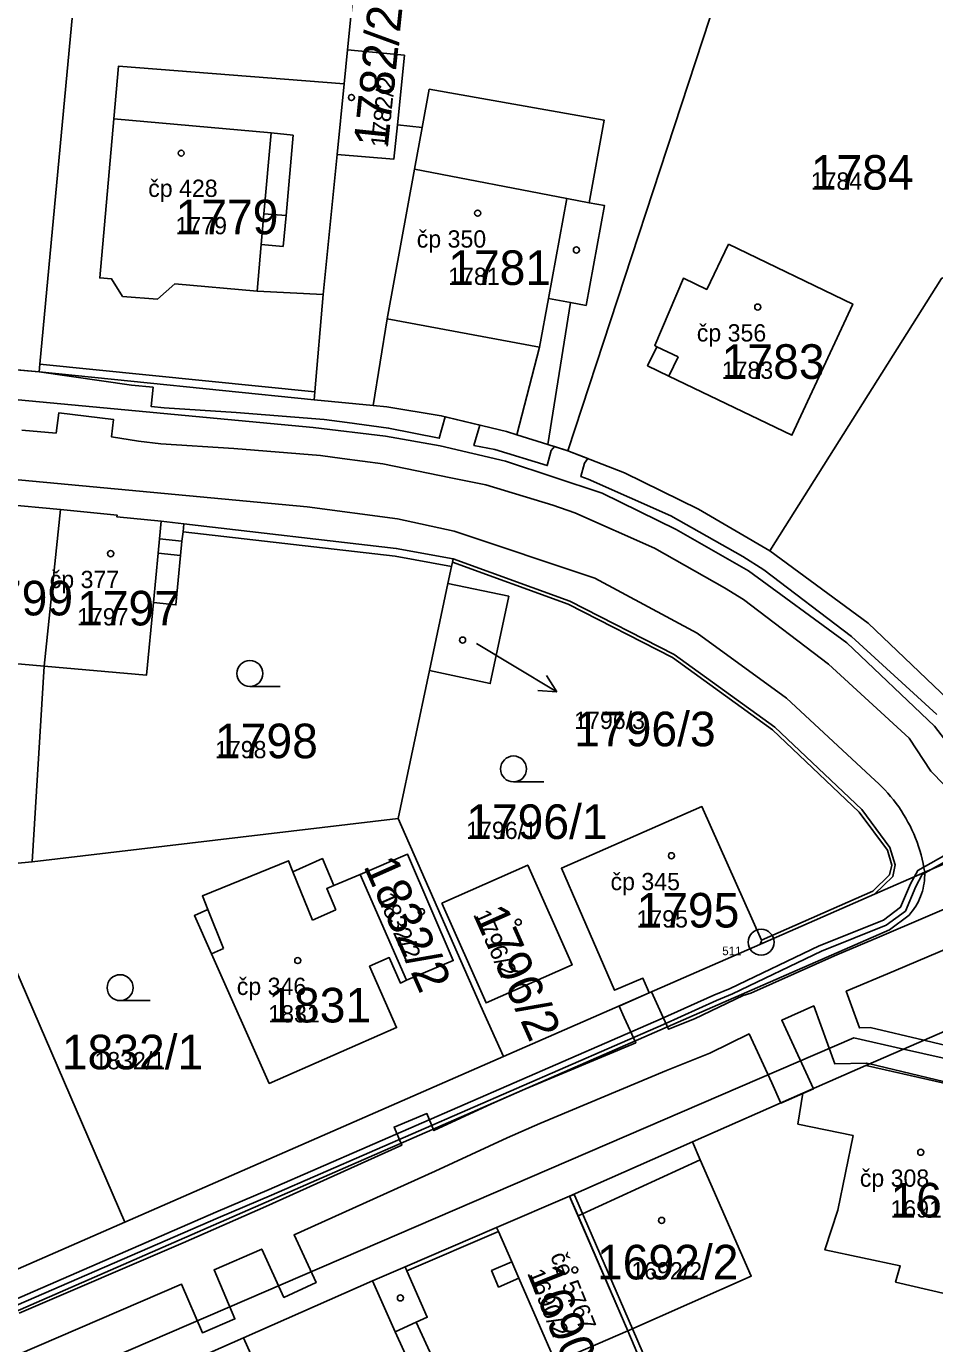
# Model space of a CAD drawing. Extents: x -763628 to -761565, y -976033 to -973833.
# Drawn here: x -762577.9 to -762525.4, y -975069 to -974992.9 of the extents above; entities that cross this region are included whole.
import ezdxf

# ---------------------------------------------------------------- set-up
doc = ezdxf.new("R2010")
doc.units = 0
for name, color, linetype in [('KN_cisla parcel 1000', 7, 'Continuous'), ('KN_cisla parcel 500', 7, 'Continuous'), ('KN_cisla parcel znacky', 7, 'Continuous'), ('KN_cisla popisna 500', 7, 'Continuous'), ('KN_hranice parcel', 7, 'Continuous'), ('KN_vecna bremena', 7, 'Continuous'), ('KN_vnitrni kresba parcel', 7, 'Continuous'), ('KN_znacky bodu BP', 7, 'Continuous'), ('KN_znacky budov', 7, 'Continuous'), ('KN_znacky kultur', 7, 'Continuous')]:
    doc.layers.add(name, color=color, linetype=linetype)

msp = doc.modelspace()

# ---------------------------------------------------------------- linework, layer by layer
at = {"layer": 'KN_cisla parcel znacky'}
for p, q in [((-762551.91, -975028.54), (-762549.82, -975029.8)), ((-762549.82, -975029.8), (-762547.248, -975031.346)), ((-762547.248, -975031.346), (-762547.848, -975030.401)), ((-762547.248, -975031.346), (-762548.364, -975031.259))]:
    msp.add_line(p, q, dxfattribs=at)
at = {"layer": 'KN_hranice parcel'}
for p, q in [((-762559.37, -974994.22), (-762557.73, -974977.61)), ((-762546.62, -975017.4), (-762535.84, -974984.54)), ((-762559.56, -974996.17), (-762559.37, -974994.22)), ((-762559.97, -975000.26), (-762559.56, -974996.17)), ((-762560.77, -975008.36), (-762559.97, -975000.26)), ((-762581.07, -975012.5), (-762577.2, -975012.84)), ((-762577.2, -975012.84), (-762561.3, -975014.45)), ((-762547.78, -975017.04), (-762546.62, -975017.4)), ((-762575.96, -975020.8), (-762576.92, -975029.86)), ((-762553.56, -975025.07), (-762554.63, -975030.11)), ((-762576.92, -975029.86), (-762577.61, -975041.17)), ((-762554.63, -975030.11), (-762556.44, -975038.66)), ((-762577.61, -975041.17), (-762556.44, -975038.66)), ((-762581.12, -975041.51), (-762577.61, -975041.17)), ((-762572.25, -975062), (-762581.12, -975041.51)), ((-762555.95, -975048.02), (-762558.64, -975041.9)), ((-762541.91, -975048.74), (-762535.52, -975045.96)), ((-762550.34, -975052.42), (-762541.91, -975048.74)), ((-762550.34, -975052.42), (-762572.25, -975062)), ((-762529.39, -975052.95), (-762533.02, -975054.55)), ((-762539.41, -975057.37), (-762533.02, -975054.55)), ((-762546.52, -975060.51), (-762539.41, -975057.37)), ((-762546.52, -975060.51), (-762550.74, -975062.32)), ((-762588.8, -975069.25), (-762572.25, -975062)), ((-762550.74, -975062.32), (-762556.04, -975064.6)), ((-762538.48, -975079.34), (-762543.16, -975068.29))]:
    msp.add_line(p, q, dxfattribs=at)
for points in [[(-762577.2, -975012.84), (-762577.16, -975012.39), (-762573.77, -974976.05)], [(-762559.37, -974994.22), (-762556.07, -974994.53), (-762556.48, -974998.56)], [(-762559.56, -974996.17), (-762572.61, -974995.15), (-762572.89, -974998.21), (-762573.7, -975007.4), (-762573.01, -975007.46), (-762572.38, -975008.47), (-762570.35, -975008.63), (-762569.35, -975007.74), (-762564.6, -975008.16), (-762560.77, -975008.36)], [(-762547.78, -975017.04), (-762546.46, -975008.83), (-762545.57, -975008.99), (-762544.5, -975003.22), (-762545.39, -975003.06), (-762544.51, -974998.29), (-762554.64, -974996.49), (-762555.04, -974998.7), (-762556.48, -974998.56)], [(-762556.48, -974998.56), (-762556.68, -975000.53), (-762559.97, -975000.26)], [(-762534.93, -975023.19), (-762525.01, -975007.43), (-762517.1, -975003.93)], [(-762537.33, -975005.45), (-762538.59, -975008.07), (-762539.94, -975007.42), (-762541.59, -975011.32), (-762541.48, -975011.38), (-762542.01, -975012.48), (-762540.77, -975013.08), (-762533.66, -975016.5), (-762530.14, -975008.92), (-762537.33, -975005.45)], [(-762561.3, -975014.45), (-762561.26, -975014), (-762560.77, -975008.36)], [(-762561.3, -975014.45), (-762557.89, -975014.78), (-762557.1, -975014.86), (-762553.94, -975015.37), (-762550.17, -975016.29), (-762549.57, -975016.48), (-762547.78, -975017.04)], [(-762546.62, -975017.4), (-762543.35, -975018.67), (-762539.07, -975020.77), (-762534.93, -975023.19)], [(-762588.4, -975019.68), (-762588.49, -975020.71), (-762589.22, -975028.68), (-762584.16, -975029.22), (-762582.84, -975029.34), (-762576.92, -975029.86)], [(-762575.96, -975020.8), (-762579.3, -975020.48), (-762579.31, -975020.58), (-762581.85, -975020.34), (-762583.18, -975020.21), (-762588.4, -975019.68)], [(-762568.83, -975021.63), (-762570.14, -975021.48), (-762572.7, -975021.22), (-762572.69, -975021.13), (-762575.96, -975020.8)], [(-762576.92, -975029.86), (-762571, -975030.38), (-762570.59, -975026.18), (-762569.29, -975026.31), (-762569.02, -975023.46), (-762568.94, -975022.63), (-762568.88, -975022.08), (-762568.83, -975021.63)], [(-762553.26, -975023.65), (-762556.55, -975023.05), (-762568.83, -975021.63)], [(-762534.93, -975023.19), (-762529.25, -975027.37), (-762524.19, -975032.19), (-762520.65, -975036.86), (-762519.19, -975037.83), (-762517.15, -975038)], [(-762553.26, -975023.65), (-762553.3, -975023.84), (-762553.35, -975024.09), (-762553.56, -975025.07)], [(-762528.89, -975043.05), (-762527.83, -975042.02), (-762527.68, -975041.35), (-762528, -975040.34), (-762529.62, -975038.15), (-762534.64, -975033.39), (-762540.48, -975029.18), (-762546.51, -975026.1), (-762553.26, -975023.65)], [(-762553.56, -975025.07), (-762550.04, -975025.81), (-762551.11, -975030.86), (-762554.63, -975030.11)], [(-762535.52, -975045.96), (-762535.44, -975045.82), (-762535.42, -975045.7), (-762538.87, -975037.98), (-762546.99, -975041.54), (-762543.92, -975048.6), (-762542.28, -975047.9), (-762542.01, -975048.52), (-762541.91, -975048.74)], [(-762517.15, -975038), (-762520.07, -975039.25), (-762525.98, -975041.77), (-762528.89, -975043.05)], [(-762556.44, -975038.66), (-762551.67, -975049.47), (-762550.34, -975052.42)], [(-762558.64, -975041.9), (-762555.9, -975040.72), (-762553.25, -975046.88), (-762555.95, -975048.02)], [(-762558.64, -975041.9), (-762560.15, -975042.54), (-762560.82, -975040.98), (-762562.53, -975041.74), (-762562.78, -975041.11), (-762567.76, -975043.14), (-762567.44, -975043.93), (-762568.22, -975044.28), (-762567.23, -975046.5), (-762563.89, -975053.99), (-762556.53, -975050.76), (-762558.09, -975047.21), (-762556.95, -975046.71), (-762556.31, -975048.18), (-762555.95, -975048.02)], [(-762553.91, -975043.56), (-762548.94, -975041.36), (-762546.38, -975047.13), (-762551.35, -975049.33), (-762553.91, -975043.56)], [(-762535.52, -975045.96), (-762535.34, -975045.88), (-762528.89, -975043.05)], [(-762510.26, -975044.64), (-762512.85, -975045.76), (-762527.2, -975052), (-762529.39, -975052.95)], [(-762521.46, -975054.75), (-762529.29, -975052.97), (-762529.39, -975052.95)], [(-762533.02, -975054.55), (-762533.31, -975056.34), (-762530.12, -975057), (-762531, -975061.31), (-762531.75, -975063.61), (-762527.39, -975064.54), (-762527.66, -975065.47), (-762523.85, -975066.37)], [(-762539.41, -975057.37), (-762538.96, -975058.41), (-762536.01, -975065.13), (-762543.16, -975068.29)], [(-762543.16, -975068.29), (-762546.03, -975061.65), (-762546.52, -975060.51)], [(-762543.16, -975068.29), (-762547.34, -975070.1), (-762549.45, -975065.25), (-762550.63, -975065.76), (-762551.03, -975064.81), (-762549.86, -975064.3), (-762550.64, -975062.55), (-762550.74, -975062.32)], [(-762556.04, -975064.6), (-762557.93, -975065.41), (-762565.38, -975068.69)], [(-762559.14, -975082.65), (-762550.28, -975078.88), (-762555.4, -975067.8), (-762554.75, -975067.51), (-762555.94, -975064.83), (-762556.04, -975064.6)], [(-762565.38, -975068.69), (-762572.42, -975071.8), (-762572.79, -975071.96), (-762573.92, -975072.46)], [(-762559.14, -975082.65), (-762561.92, -975076.42), (-762565.38, -975068.69)]]:
    msp.add_lwpolyline(points, dxfattribs=at)
at = {"layer": 'KN_vecna bremena'}
for points in [[(-762525.27, -975032.65), (-762530.21, -975028.14), (-762535.28, -975024.28), (-762536.5, -975023.52), (-762540.67, -975021.17), (-762545.45, -975019.04), (-762545.87, -975018.89), (-762545.65, -975018.11), (-762545.47, -975017.85), (-762546.62, -975017.4), (-762547.4, -975017.16), (-762547.58, -975017.39), (-762547.81, -975018.26), (-762550.85, -975017.33), (-762552.05, -975017.09), (-762551.72, -975015.91), (-762553.71, -975015.43), (-762554.06, -975016.68), (-762556.99, -975016.09), (-762559.39, -975015.76), (-762560.71, -975015.59), (-762565.8, -975015.18), (-762569.97, -975014.92), (-762570.73, -975014.83), (-762570.61, -975013.73), (-762571.86, -975013.61), (-762577.2, -975012.84), (-762579.99, -975012.59)], [(-762578.2, -975016.21), (-762576.22, -975016.38), (-762576.06, -975015.2), (-762572.91, -975015.59), (-762573.01, -975016.6), (-762571.46, -975016.85), (-762570.16, -975017), (-762565.95, -975017.26), (-762560.93, -975017.67), (-762559.67, -975017.84), (-762557.33, -975018.15), (-762553.39, -975018.96), (-762551.36, -975019.36), (-762547.48, -975020.54), (-762546.21, -975020.98), (-762541.61, -975023.03), (-762537.56, -975025.32), (-762536.46, -975026), (-762531.55, -975029.74), (-762526.87, -975034.01), (-762525.63, -975035.93), (-762521.7, -975039.94)], [(-762520.85, -975038.55), (-762526.38, -975041.67), (-762526.8, -975042.45), (-762527.37, -975043.8), (-762528.36, -975044.54), (-762532.09, -975046.02), (-762537.23, -975048.49), (-762538.17, -975048.88), (-762541.22, -975050.25), (-762563.89, -975060.12), (-762566.98, -975061.44), (-762579.08, -975066.7), (-762580.52, -975067), (-762580.79, -975067.8), (-762578.61, -975072.48)], [(-762578.27, -975072.42), (-762580.43, -975067.78), (-762580.26, -975067.3), (-762578.98, -975067.02), (-762566.84, -975061.76), (-762563.77, -975060.44), (-762541.08, -975050.57), (-762538.03, -975049.2), (-762537.09, -975048.81), (-762531.95, -975046.34), (-762528.2, -975044.84), (-762527.09, -975044.02), (-762526.5, -975042.59), (-762526.12, -975041.91), (-762520.81, -975038.93)], [(-762520.88, -975042.21), (-762528.6, -975045.51), (-762531.07, -975046.55), (-762532.27, -975047.08), (-762536.04, -975048.76), (-762536.47, -975048.91), (-762539.29, -975050.25), (-762540.79, -975050.85), (-762541.5, -975049.33), (-762541.79, -975048.69), (-762541.91, -975048.74), (-762543.66, -975049.51), (-762543.37, -975050.17), (-762542.69, -975051.63), (-762549.11, -975054.32), (-762551.03, -975055.16), (-762554.37, -975056.71), (-762554.77, -975055.73), (-762556.67, -975056.51), (-762556.23, -975057.56), (-762564.1, -975061.1), (-762568.88, -975063.2), (-762578.35, -975067.28)], [(-762522.99, -975052.22), (-762526.03, -975051.49), (-762529.14, -975050.75), (-762529.75, -975050.78), (-762530.52, -975048.66), (-762527.76, -975047.49), (-762520, -975044.19)], [(-762578.46, -975069.68), (-762568.97, -975065.59), (-762567.76, -975068.4), (-762565.88, -975067.6), (-762567.08, -975064.77), (-762564.33, -975063.57), (-762563.04, -975066.36), (-762561.18, -975065.5), (-762562.46, -975062.74), (-762554.3, -975059.06), (-762550.14, -975057.14), (-762548.25, -975056.31), (-762540.92, -975053.23), (-762538.41, -975052.23), (-762536.14, -975051.12), (-762534.83, -975053.95), (-762534.3, -975055.12), (-762532.42, -975054.29), (-762532.97, -975053.09), (-762534.25, -975050.33), (-762532.4, -975049.5), (-762531.18, -975052.85), (-762529.34, -975052.81), (-762529.16, -975052.85), (-762523.45, -975054.22)]]:
    msp.add_lwpolyline(points, dxfattribs=at)
msp.add_lwpolyline([(-762546.26, -975060.4), (-762546.52, -975060.51), (-762546.42, -975060.74), (-762543.16, -975068.29), (-762538.48, -975079.34), (-762538.11, -975079.18), (-762542.89, -975068.17), (-762546.16, -975060.63)], close=True, dxfattribs=at)
at = {"layer": 'KN_vnitrni kresba parcel'}
for p, q in [((-762563.79, -974999.02), (-762572.89, -974998.21)), ((-762555.04, -974998.7), (-762555.49, -975001.12)), ((-762564.2, -975003.69), (-762563.79, -974999.02)), ((-762563.79, -974999.02), (-762562.5, -974999.14)), ((-762562.5, -974999.14), (-762562.91, -975003.8)), ((-762557.08, -975009.77), (-762555.49, -975001.12)), ((-762555.49, -975001.12), (-762546.67, -975002.82)), ((-762546.67, -975002.82), (-762547.74, -975008.59)), ((-762546.67, -975002.82), (-762545.39, -975003.06)), ((-762564.36, -975005.48), (-762564.2, -975003.69)), ((-762562.91, -975003.8), (-762564.2, -975003.69)), ((-762562.91, -975003.8), (-762563.08, -975005.59)), ((-762564.6, -975008.16), (-762564.36, -975005.48)), ((-762563.08, -975005.59), (-762564.36, -975005.48)), ((-762652.12, -975007.59), (-762561.36, -975016.05)), ((-762548.26, -975011.4), (-762547.74, -975008.59)), ((-762547.74, -975008.59), (-762546.46, -975008.83)), ((-762557.89, -975014.78), (-762557.08, -975009.77)), ((-762557.08, -975009.77), (-762548.26, -975011.4)), ((-762549.57, -975016.48), (-762548.26, -975011.4)), ((-762540.23, -975011.97), (-762541.48, -975011.38)), ((-762653.54, -975012.07), (-762561.7, -975020.64)), ((-762577.16, -975012.39), (-762561.26, -975014)), ((-762540.77, -975013.08), (-762540.23, -975011.97)), ((-762561.36, -975016.05), (-762557.16, -975016.56)), ((-762557.16, -975016.56), (-762554, -975017.12)), ((-762554, -975017.12), (-762550.23, -975018)), ((-762550.23, -975018), (-762544.64, -975019.86)), ((-762544.64, -975019.86), (-762540.35, -975021.95)), ((-762561.7, -975020.64), (-762556.48, -975021.33)), ((-762570.14, -975021.48), (-762570.24, -975022.5)), ((-762556.48, -975021.33), (-762553.2, -975022.05)), ((-762556.6, -975023.5), (-762568.88, -975022.08)), ((-762553.2, -975022.05), (-762545.06, -975024.76)), ((-762540.35, -975021.95), (-762536.18, -975024.34)), ((-762570.32, -975023.33), (-762570.24, -975022.5)), ((-762568.94, -975022.63), (-762570.24, -975022.5)), ((-762570.32, -975023.33), (-762570.59, -975026.18)), ((-762570.32, -975023.33), (-762569.02, -975023.46)), ((-762553.35, -975024.09), (-762556.6, -975023.5)), ((-762546.6, -975026.28), (-762553.3, -975023.84)), ((-762545.06, -975024.76), (-762539.14, -975027.94)), ((-762536.18, -975024.34), (-762530.48, -975028.5)), ((-762540.57, -975029.36), (-762546.6, -975026.28)), ((-762539.14, -975027.94), (-762533.97, -975031.71)), ((-762530.48, -975028.5), (-762525.42, -975033.32)), ((-762534.78, -975033.54), (-762540.57, -975029.36)), ((-762533.97, -975031.71), (-762528.84, -975036.47)), ((-762529.76, -975038.3), (-762534.78, -975033.54)), ((-762525.42, -975033.32), (-762521.86, -975037.98)), ((-762528.13, -975040.5), (-762529.76, -975038.3)), ((-762527.88, -975041.36), (-762528.13, -975040.5)), ((-762528.01, -975041.93), (-762527.88, -975041.36)), ((-762562.53, -975041.74), (-762561.4, -975044.55)), ((-762528.97, -975042.87), (-762528.01, -975041.93)), ((-762535.42, -975045.7), (-762528.97, -975042.87)), ((-762567.44, -975043.93), (-762566.53, -975046.19)), ((-762561.4, -975044.55), (-762560.05, -975043.95)), ((-762528.01, -975045.1), (-762526.88, -975044.25)), ((-762587.93, -975071.28), (-762528.01, -975045.1)), ((-762567.23, -975046.5), (-762566.53, -975046.19)), ((-762581, -975073.28), (-762530.07, -975051.35)), ((-762530.07, -975051.35), (-762527.2, -975052)), ((-762527.2, -975052), (-762512.88, -975055.25)), ((-762546.03, -975061.65), (-762538.96, -975058.41)), ((-762555.94, -975064.83), (-762550.64, -975062.55)), ((-762549.86, -975064.3), (-762549.45, -975065.25)), ((-762556.6, -975068.35), (-762557.93, -975065.41)), ((-762555.4, -975067.8), (-762556.6, -975068.35)), ((-762554.43, -975073.16), (-762556.6, -975068.35))]:
    msp.add_line(p, q, dxfattribs=at)
for points in [[(-762528.84, -975036.47), (-762528.651, -975036.643), (-762528.468, -975036.822), (-762528.29, -975037.006), (-762528.117, -975037.194), (-762527.949, -975037.388), (-762527.788, -975037.587), (-762527.632, -975037.79), (-762527.482, -975037.998), (-762527.338, -975038.21), (-762527.201, -975038.425), (-762527.069, -975038.645), (-762526.945, -975038.869), (-762526.826, -975039.096), (-762526.715, -975039.326), (-762526.61, -975039.56), (-762526.511, -975039.796), (-762526.42, -975040.036), (-762526.336, -975040.277), (-762526.259, -975040.522), (-762526.189, -975040.768), (-762526.126, -975041.016), (-762526.07, -975041.266), (-762526.021, -975041.517), (-762525.98, -975041.77)], [(-762526.88, -975044.25), (-762526.776, -975044.129), (-762526.678, -975044.004), (-762526.586, -975043.875), (-762526.5, -975043.741), (-762526.419, -975043.604), (-762526.345, -975043.463), (-762526.278, -975043.319), (-762526.217, -975043.172), (-762526.163, -975043.022), (-762526.115, -975042.871), (-762526.075, -975042.717), (-762526.041, -975042.561), (-762526.015, -975042.404), (-762525.995, -975042.247), (-762525.983, -975042.088), (-762525.978, -975041.929), (-762525.98, -975041.77)], [(-762560.05, -975043.95), (-762560.57, -975042.72), (-762560.15, -975042.54)]]:
    msp.add_lwpolyline(points, dxfattribs=at)
at = {"layer": 'KN_znacky bodu BP'}
for radius in [0.75, 0.03]:
    msp.add_circle((-762535.44, -975045.82), radius, dxfattribs=at)
at = {"layer": 'KN_znacky budov'}
for centre in [(-762559.137, -974996.969), (-762568.987, -975000.189), (-762551.837, -975003.659), (-762546.127, -975005.789), (-762535.637, -975009.089), (-762573.067, -975023.349), (-762552.707, -975028.349), (-762540.627, -975040.819), (-762555.097, -975044.059), (-762549.487, -975044.659), (-762562.247, -975046.879), (-762526.207, -975057.969), (-762541.197, -975061.909), (-762546.217, -975064.769), (-762556.307, -975066.389)]:
    msp.add_circle(centre, 0.175, dxfattribs=at)
at = {"layer": 'KN_znacky kultur'}
for p, q in [((-762565.013, -975031.03), (-762563.263, -975031.03)), ((-762549.763, -975036.55), (-762548.013, -975036.55)), ((-762572.523, -975049.2), (-762570.773, -975049.2))]:
    msp.add_line(p, q, dxfattribs=at)
for centre in [(-762565.013, -975030.28), (-762549.763, -975035.8), (-762572.523, -975048.45)]:
    msp.add_circle(centre, 0.75, dxfattribs=at)

# ---------------------------------------------------------------- texts
at = {"layer": 'KN_cisla parcel 1000'}
for s, rotation, p in [('1782/2', 84, (-762557.035, -974999.905)), ('1832/2', 294, (-762558.466, -975041.402)), ('1796/2', 294, (-762552.116, -975044.214)), ('1690/2', 292, (-762548.99, -975064.953))]:
    msp.add_text(s, height=2, rotation=rotation, dxfattribs=at).set_placement(p)
for s, p in [('1784', (-762532.57, -975002.3)), ('1779', (-762569.313, -975004.879)), ('1781', (-762553.54, -975007.81)), ('1783', (-762537.72, -975013.24)), ('1799', (-762581.19, -975026.92)), ('1797', (-762575.01, -975027.5)), ('1796/3', (-762546.25, -975034.488)), ('1798', (-762567.03, -975035.18)), ('1796/1', (-762552.5, -975039.85)), ('1795', (-762542.65, -975044.97)), ('1831', (-762563.95, -975050.46)), ('1832/1', (-762575.89, -975053.17)), ('1691', (-762527.96, -975061.74)), ('1692/2', (-762544.932, -975065.32))]:
    msp.add_text(s, height=2, dxfattribs=at).set_placement(p)
at = {"layer": 'KN_cisla parcel 500'}
for s, rotation, p in [('1782/2', 84, (-762557.035, -974999.905)), ('1832/2', 294, (-762557.66, -975043.214)), ('1796/2', 294, (-762552.116, -975044.214)), ('1690/2', 292, (-762548.99, -975064.953))]:
    msp.add_text(s, height=1, rotation=rotation, dxfattribs=at).set_placement(p)
for s, p in [('1784', (-762532.57, -975002.3)), ('1779', (-762569.313, -975004.879)), ('1781', (-762553.54, -975007.81)), ('1783', (-762537.72, -975013.24)), ('1797', (-762575.01, -975027.5)), ('1796/3', (-762546.25, -975033.488)), ('1798', (-762567.03, -975035.18)), ('1796/1', (-762552.5, -975039.85)), ('1795', (-762542.65, -975044.97)), ('1831', (-762563.95, -975050.46)), ('1832/1', (-762574.006, -975053.17)), ('1691', (-762527.96, -975061.74)), ('1692/2', (-762542.949, -975065.32))]:
    msp.add_text(s, height=1, dxfattribs=at).set_placement(p)
at = {"layer": 'KN_cisla popisna 500'}
for s, p in [('čp 428', (-762570.894, -975002.72)), ('čp 350', (-762555.361, -975005.651)), ('čp 356', (-762539.161, -975011.081)), ('čp 377', (-762576.591, -975025.341)), ('čp 345', (-762544.151, -975042.811)), ('čp 346', (-762565.771, -975048.871)), ('čp 308', (-762529.731, -975059.961))]:
    msp.add_text(s, height=1, dxfattribs=at).set_placement(p)
msp.add_text('če 5767', height=1, rotation=292, dxfattribs=at).set_placement((-762547.658, -975063.964))
at = {"layer": 'KN_znacky bodu BP'}
msp.add_text('511', height=0.5, dxfattribs=at).set_placement((-762537.688, -975046.57))

doc.saveas('drawing.dxf')
